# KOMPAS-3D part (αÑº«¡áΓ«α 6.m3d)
File: created 29.01.2016 13:47:21, last saved 27.07.2016 15:00:17.
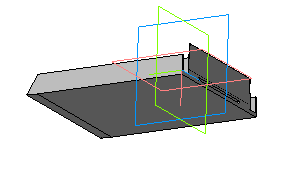
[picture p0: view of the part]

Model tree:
1. Эскиз:1
2. Операция выдавливания:1
     Толщина стенки 1 = 2; Толщина стенки 2 = 8; Расстояние 1 = 1
3. Эскиз:2
4. Операция выдавливания:2
     Толщина стенки 1 = 2; Толщина стенки 2 = 8; Расстояние 1 = 5
5. Эскиз:3
6. Операция выдавливания:3
     Толщина стенки 1 = 2; Толщина стенки 2 = 8; Расстояние 1 = 1
7. Эскиз:4
8. Операция выдавливания:4
     Толщина стенки 1 = 2; Толщина стенки 2 = 2.5; Расстояние 1 = 50
9. Эскиз:5
10. Вырезать элемент выдавливания:1
     Толщина стенки 2 = 1.2; Расстояние 1 = 40
11. Эскиз:6
12. Операция выдавливания:5
     Толщина стенки 1 = 2; Толщина стенки 2 = 2.5; Расстояние 1 = 10
13. Эскиз:7
14. Операция выдавливания:6
     Толщина стенки 1 = 2; Толщина стенки 2 = 8; Расстояние 1 = 1
15. Эскиз:8
16. Операция выдавливания:7
     Толщина стенки 1 = 2; Толщина стенки 2 = 8; Расстояние 1 = 5
17. Эскиз:9
18. Операция выдавливания:8
     Толщина стенки 1 = 2; Толщина стенки 2 = 8; Расстояние 1 = 1
19. Эскиз:10
20. Вырезать элемент выдавливания:2
     Толщина стенки 2 = 1.2; Расстояние 1 = 23
21. Эскиз:11
22. Вырезать элемент выдавливания:3
     Толщина стенки 2 = 1.2; Расстояние 1 = 1
23. Эскиз:12
24. Вырезать элемент выдавливания:4
     Расстояние 1 = 100
25. Эскиз:17
26. Операция выдавливания:13
     Расстояние 1 = 10; Расстояние 2 = 0.4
